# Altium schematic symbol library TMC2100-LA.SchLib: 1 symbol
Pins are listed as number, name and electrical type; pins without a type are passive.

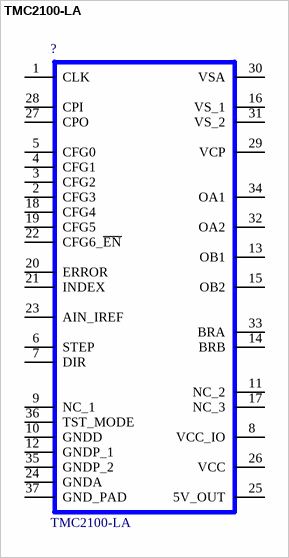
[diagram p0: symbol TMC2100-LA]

## TMC2100-LA
designator ?
Universal high voltage driver for two-phase bipolar stepper motor, Step/Dir, QFN36_5x6; Manufacturer: TRINAMIC; Geometry.Height: 0,9mm; Ordercode - Distri#1: 1460-1128-1-ND
footprint TMC_QFN36_0.5_5.0X6.0
pins: 1 CLK, 2 CFG3, 3 CFG2, 4 CFG1, 5 CFG0, 6 STEP, 7 DIR, 8 VCC_IO (power), 9 NC_1, 10 GNDD, 11 NC_2, 12 GNDP_1, 13 OB1, 14 BRB, 15 OB2, 16 VS_1 (power), 17 NC_3, 18 CFG4, 19 CFG5, 20 ERROR (oc), 21 INDEX (oc), 22 CFG6_~{EN}, 23 AIN_IREF, 24 GNDA, 25 5V_OUT (power), 26 VCC (power), 27 CPO, 28 CPI, 29 VCP (power), 30 VSA (power), 31 VS_2 (power), 32 OA2, 33 BRA, 34 OA1, 35 GNDP_2, 36 TST_MODE, 37 GND_PAD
